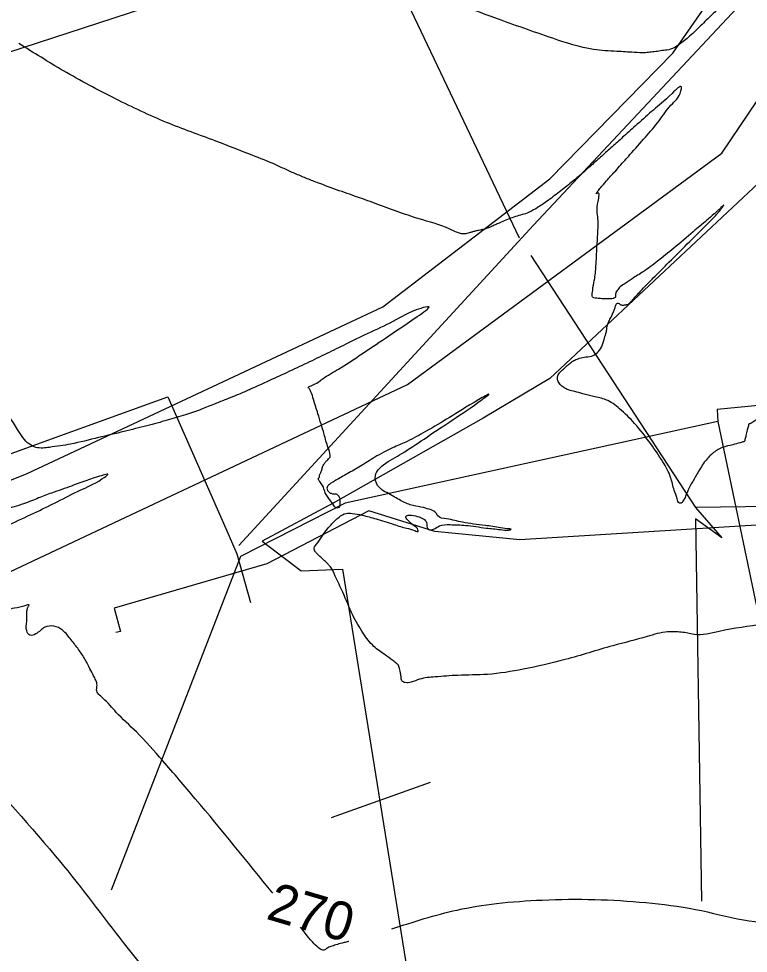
# Model space of a CAD drawing. Extents: x -478464 to -472469, y -1118040 to -1113785.
# Drawn here: x -475618 to -475541.9, y -1115586.5 to -1115489 of the extents above; entities that cross this region are included whole.
import ezdxf

# ---------------------------------------------------------------- set-up
doc = ezdxf.new("R2010")
doc.units = 0
for name, color, linetype in [('el vedeni_NN', 7, 'Continuous'), ('meliorace', 7, 'Continuous'), ('ObPÚ', 7, 'Continuous'), ('plyn_ntl', 7, 'Continuous'), ('plyn_stl', 7, 'Continuous'), ('silnice', 7, 'Continuous'), ('telekomunikační kabel_O2', 7, 'Continuous'), ('VAK_vodovod_přípojky', 7, 'Continuous'), ('Vrstevnice_hlavni', 7, 'Continuous'), ('Vrstevnice_popis', 7, 'Continuous'), ('Vrstevnice_vedlejsi', 7, 'Continuous')]:
    doc.layers.add(name, color=color, linetype=linetype)

msp = doc.modelspace()

# ---------------------------------------------------------------- linework, layer by layer
at = {"layer": 'el vedeni_NN'}
for points in [[(-475377.782, -1115185.638), (-475361.891, -1115178.13), (-475377.677, -1115209.214), (-475398.727, -1115246.374), (-475420.31, -1115282.665), (-475460.363, -1115351.777), (-475479.026, -1115383.225), (-475499.115, -1115417.348), (-475520.351, -1115454.7), (-475542.566, -1115487.377), (-475564.331, -1115510.556), (-475595.07, -1115543.98)], [(-475592.1, -1115463.897), (-475577.122, -1115488.137), (-475565.808, -1115511.875)], [(-475564.609, -1115513.741), (-475547.415, -1115540.02), (-475544.656, -1115543.188), (-475547.4, -1115541.22), (-475546.96, -1115569.997), (-475546.789, -1115581.094)], [(-475483.347, -1115539.435), (-475513.399, -1115539.58), (-475547.415, -1115540.02)]]:
    msp.add_lwpolyline(points, dxfattribs=at)
at = {"layer": 'meliorace'}
msp.add_lwpolyline([(-475519.056, -1115308.142), (-475545.726, -1115356.957), (-475549.536, -1115401.01), (-475559.95, -1115433.157), (-475565.538, -1115475.067), (-475653.93, -1115503.88), (-475665.614, -1115491.736), (-475684.918, -1115489.117), (-475721.748, -1115507.929), (-475797.44, -1115540.314), (-475827.158, -1115551.982), (-475834.778, -1115588.653), (-475852.304, -1115592.225), (-475851.034, -1115628.896), (-475881.514, -1115644.612), (-475900.056, -1115592.463), (-475924.694, -1115605.798), (-475930.282, -1115570.794), (-475926.218, -1115555.554), (-475925.202, -1115548.41), (-475930.536, -1115473.639), (-475966.096, -1115498.642)], dxfattribs=at)
at = {"layer": 'ObPÚ'}
for points in [[(-475728.43, -1115519.24), (-475712.42, -1115512.73), (-475696.58, -1115506.62), (-475678.04, -1115499.14), (-475661.39, -1115542.5), (-475657.48, -1115552.74), (-475617.15, -1115536.48), (-475580.03, -1115519.1), (-475562.62, -1115505.75), (-475549.77, -1115492.64), (-475525.8, -1115458.18)], [(-475534.81, -1115500.57), (-475562.61, -1115526.56), (-475569.57, -1115530.71), (-475585.22, -1115539.58), (-475592.62, -1115543.55), (-475588.56, -1115546.64), (-475584.24, -1115546.47), (-475575.51, -1115600.67), (-475574.56, -1115606.97), (-475568.59, -1115650.37), (-475601.06, -1115656.55), (-475624.46, -1115661.25), (-475654.25, -1115666.44), (-475684.32, -1115671.28), (-475687.18, -1115670.63), (-475693.69, -1115674.84), (-475698.97, -1115680.1), (-475705.68, -1115683.92), (-475709.84, -1115683.94), (-475733.4, -1115683.13)]]:
    msp.add_lwpolyline(points, dxfattribs=at)
at = {"layer": 'plyn_ntl'}
msp.add_line((-475585.38, -1115572.37), (-475575.07, -1115568.66), dxfattribs=at)
at = {"layer": 'plyn_stl'}
msp.add_lwpolyline([(-475699.229, -1115569.389), (-475682.71, -1115562.73), (-475680.94, -1115561.92), (-475675.76, -1115558.44), (-475667.15, -1115553.51), (-475655.03, -1115549.33), (-475634.75, -1115540.12), (-475625, -1115536.6), (-475613.74, -1115532.535), (-475602.48, -1115528.47), (-475596.433, -1115542.197), (-475595.26, -1115544.86), (-475593.843, -1115549.92)], dxfattribs=at)
at = {"layer": 'silnice'}
msp.add_lwpolyline([(-476261.922, -1115907.288), (-476203.622, -1115869.922), (-476022.083, -1115758.582), (-475811.314, -1115629.283), (-475771.826, -1115610.299), (-475706.185, -1115581.566), (-475629.775, -1115551.807), (-475577.467, -1115527.178), (-475544.647, -1115503.063), (-475523.184, -1115471.236), (-475482.102, -1115402.498), (-475367.21, -1115204.445), (-475326.334, -1115129.255), (-475275.418, -1115058.05)], dxfattribs=at)
at = {"layer": 'telekomunikační kabel_O2'}
for points in [[(-475539.93, -1115541.78), (-475565.75, -1115543.38), (-475574.63, -1115542.51), (-475581.49, -1115540.36), (-475592.14, -1115545.91), (-475608.07, -1115550.52)], [(-475608.07, -1115550.52), (-475607.42, -1115552.94)], [(-475607.42, -1115552.94), (-475607.9, -1115553.07)]]:
    msp.add_lwpolyline(points, dxfattribs=at)
at = {"layer": 'VAK_vodovod_přípojky'}
for points in [[(-475400.788, -1115513.502), (-475400.524, -1115515.774), (-475545.153, -1115529.786), (-475545.079, -1115531.049), (-475540.879, -1115551.163)], [(-475545.079, -1115531.049), (-475583.983, -1115539.581), (-475594.886, -1115545.125), (-475608.399, -1115579.932)]]:
    msp.add_lwpolyline(points, dxfattribs=at)
at = {"layer": 'Vrstevnice_hlavni'}
for points in [[(-475591.524, -1115580.265), (-475599.609, -1115570.405), (-475603.006, -1115566.438), (-475605.756, -1115563.433), (-475607.86, -1115561.392), (-475609.247, -1115559.923), (-475609.92, -1115559.026), (-475609.876, -1115558.701), (-475609.874, -1115558.427), (-475609.913, -1115558.202), (-475609.993, -1115558.028), (-475610.223, -1115557.577), (-475610.602, -1115556.848), (-475611.13, -1115555.843), (-475611.784, -1115554.838), (-475612.563, -1115553.834), (-475613.468, -1115552.831), (-475614.385, -1115552.392), (-475615.315, -1115552.518), (-475616.257, -1115553.208), (-475616.885, -1115553.334), (-475617.199, -1115552.896), (-475617.199, -1115551.894), (-475617.188, -1115551.171), (-475617.165, -1115550.727), (-475617.132, -1115550.563), (-475617.087, -1115550.424), (-475617.03, -1115550.311), (-475616.962, -1115550.223), (-475617.522, -1115550.307), (-475618.71, -1115550.562), (-475620.526, -1115550.989), (-475621.889, -1115550.589), (-475622.798, -1115549.362), (-475623.254, -1115547.307), (-475623.56, -1115545.905), (-475623.717, -1115545.155), (-475623.725, -1115545.056), (-475623.491, -1115544.778), (-475623.016, -1115544.322), (-475622.3, -1115543.687), (-475621.816, -1115543.259), (-475621.564, -1115543.038), (-475621.544, -1115543.024), (-475620.687, -1115542.614), (-475618.993, -1115541.808), (-475616.462, -1115540.607), (-475614.01, -1115539.413), (-475611.639, -1115538.226), (-475609.348, -1115537.047), (-475608.735, -1115536.58), (-475609.8, -1115536.824), (-475612.543, -1115537.779), (-475614.606, -1115538.515), (-475615.988, -1115539.03), (-475616.689, -1115539.326), (-475617.534, -1115539.633), (-475618.524, -1115539.952), (-475619.658, -1115540.284), (-475621.024, -1115540.684), (-475622.622, -1115541.153), (-475624.451, -1115541.691), (-475625.936, -1115541.98), (-475627.075, -1115542.019), (-475627.87, -1115541.808), (-475628.975, -1115541.71), (-475630.391, -1115541.727), (-475632.117, -1115541.857), (-475633.269, -1115541.944), (-475633.845, -1115541.987), (-475633.846, -1115541.988), (-475633.935, -1115541.311), (-475634.111, -1115539.956), (-475634.376, -1115537.925), (-475634.629, -1115536.449), (-475634.872, -1115535.531), (-475635.105, -1115535.169), (-475636.099, -1115533.281), (-475637.853, -1115529.865), (-475640.368, -1115524.923), (-475642.128, -1115521.35), (-475643.132, -1115519.146), (-475643.38, -1115518.311), (-475643.745, -1115517.543), (-475644.228, -1115516.841), (-475644.827, -1115516.206), (-475645.294, -1115515.535), (-475645.627, -1115514.826), (-475645.827, -1115514.081), (-475646.265, -1115513.152), (-475646.941, -1115512.04), (-475647.855, -1115510.744), (-475648.331, -1115509.199), (-475648.37, -1115507.406), (-475647.972, -1115505.363), (-475647.723, -1115503.798), (-475647.624, -1115502.709)], [(-475579.109, -1115583.986), (-475572.285, -1115582.012), (-475568.185, -1115581.335), (-475563.397, -1115580.969), (-475557.92, -1115580.913), (-475552.593, -1115581.239), (-475547.416, -1115581.947), (-475542.388, -1115583.036), (-475537.622, -1115583.501), (-475533.118, -1115583.341), (-475528.876, -1115582.557), (-475523.989, -1115580.76), (-475518.456, -1115577.95), (-475512.277, -1115574.126), (-475511.964, -1115573.95)], [(-475583.591, -1115585.283), (-475583.637, -1115585.296), (-475583.865, -1115585.358), (-475584.299, -1115585.475), (-475584.938, -1115585.646), (-475585.465, -1115585.826), (-475585.881, -1115586.013), (-475586.186, -1115586.209), (-475586.627, -1115586.048), (-475587.204, -1115585.533), (-475588.634, -1115583.79)]]:
    msp.add_spline(points, degree=3, dxfattribs=at)
at = {"layer": 'Vrstevnice_vedlejsi'}
for points in [[(-475534.31, -1115479.622), (-475534.205, -1115479.458), (-475534.115, -1115479.315), (-475534.039, -1115479.195), (-475533.977, -1115479.098), (-475533.581, -1115478.429), (-475532.85, -1115477.189), (-475531.786, -1115475.378), (-475530.838, -1115473.747), (-475530.007, -1115472.296), (-475529.292, -1115471.025), (-475528.094, -1115468.828), (-475526.411, -1115465.706), (-475524.244, -1115461.658), (-475523.771, -1115460.37), (-475524.992, -1115461.841), (-475527.906, -1115466.073), (-475530.332, -1115469.593), (-475532.269, -1115472.402), (-475533.717, -1115474.5), (-475534.831, -1115476.125), (-475535.61, -1115477.276), (-475536.055, -1115477.955), (-475536.59, -1115478.738), (-475537.214, -1115479.626), (-475537.927, -1115480.619), (-475538.842, -1115481.699), (-475539.957, -1115482.868), (-475541.273, -1115484.126), (-475542.465, -1115485.298), (-475543.534, -1115486.384), (-475544.478, -1115487.385), (-475545.541, -1115488.465), (-475546.724, -1115489.626), (-475548.026, -1115490.867), (-475549.129, -1115491.733), (-475550.035, -1115492.224), (-475550.742, -1115492.34), (-475551.408, -1115492.437), (-475552.033, -1115492.516), (-475552.616, -1115492.577), (-475553.813, -1115492.551), (-475555.625, -1115492.438), (-475558.052, -1115492.239), (-475562.296, -1115491.075), (-475568.357, -1115488.947), (-475576.235, -1115485.855), (-475583.123, -1115482.7), (-475589.02, -1115479.485), (-475593.926, -1115476.207), (-475598.667, -1115473.276), (-475601.18, -1115471.837)], [(-475587.754, -1115527.573), (-475587.805, -1115527.556), (-475587.308, -1115527.218), (-475586.26, -1115526.559), (-475584.664, -1115525.578), (-475582.499, -1115524.177), (-475579.767, -1115522.355), (-475576.467, -1115520.112), (-475575.24, -1115519.076), (-475576.086, -1115519.248), (-475579.006, -1115520.626), (-475581.614, -1115521.871), (-475583.91, -1115522.984), (-475585.893, -1115523.964), (-475587.936, -1115524.948), (-475590.038, -1115525.937), (-475592.198, -1115526.931), (-475593.833, -1115527.671), (-475594.942, -1115528.158), (-475595.526, -1115528.392), (-475596.393, -1115528.74), (-475597.544, -1115529.202), (-475598.978, -1115529.777), (-475600.642, -1115530.35), (-475602.535, -1115530.92), (-475604.657, -1115531.486), (-475607.048, -1115532.09), (-475609.707, -1115532.73), (-475612.634, -1115533.406), (-475614.811, -1115533.747), (-475616.238, -1115533.753), (-475616.915, -1115533.424), (-475618.153, -1115531.882), (-475619.952, -1115529.128), (-475622.313, -1115525.162), (-475624.203, -1115521.896), (-475625.623, -1115519.329), (-475626.573, -1115517.462), (-475627.223, -1115516.164), (-475627.571, -1115515.436), (-475627.619, -1115515.276), (-475627.688, -1115515.129), (-475627.781, -1115514.995), (-475627.895, -1115514.873), (-475627.985, -1115514.745), (-475628.048, -1115514.609), (-475628.087, -1115514.467), (-475628.17, -1115514.289), (-475628.3, -1115514.076), (-475628.474, -1115513.828), (-475628.566, -1115513.533), (-475628.573, -1115513.19), (-475628.497, -1115512.799), (-475628.449, -1115512.5), (-475628.43, -1115512.292), (-475628.44, -1115512.175), (-475628.549, -1115511.868), (-475628.759, -1115511.372), (-475629.068, -1115510.687), (-475630.244, -1115508.031), (-475632.289, -1115503.403), (-475635.2, -1115496.804), (-475637.318, -1115492.11), (-475638.486, -1115489.639)], [(-475558.11, -1115517.06), (-475557.932, -1115516.133), (-475557.787, -1115514.622), (-475557.674, -1115512.527), (-475557.594, -1115509.849), (-475557.583, -1115508.082), (-475557.642, -1115507.228), (-475557.772, -1115507.286), (-475557.659, -1115507.093), (-475557.304, -1115506.649), (-475556.707, -1115505.954), (-475556.29, -1115505.472), (-475556.053, -1115505.205), (-475555.996, -1115505.151), (-475555.949, -1115505.107), (-475555.912, -1115505.072), (-475555.885, -1115505.046), (-475555.33, -1115504.422), (-475554.247, -1115503.201), (-475552.636, -1115501.382), (-475551.213, -1115499.67), (-475549.977, -1115498.066), (-475548.93, -1115496.57), (-475548.886, -1115496.153), (-475549.846, -1115496.815), (-475551.81, -1115498.555), (-475553.486, -1115500.044), (-475554.874, -1115501.282), (-475555.974, -1115502.268), (-475557.062, -1115503.241), (-475558.141, -1115504.199), (-475559.209, -1115505.143), (-475560.369, -1115506.11), (-475561.62, -1115507.099), (-475562.963, -1115508.111), (-475564.087, -1115508.85), (-475564.994, -1115509.316), (-475565.682, -1115509.509), (-475566.362, -1115509.731), (-475567.034, -1115509.982), (-475567.698, -1115510.262), (-475568.229, -1115510.491), (-475568.627, -1115510.669), (-475568.892, -1115510.797), (-475569.232, -1115510.916), (-475569.646, -1115511.028), (-475570.135, -1115511.133), (-475570.485, -1115511.213), (-475570.697, -1115511.269), (-475570.77, -1115511.3), (-475570.911, -1115511.342), (-475571.119, -1115511.394), (-475571.395, -1115511.457), (-475573.107, -1115510.961), (-475576.256, -1115509.908), (-475580.843, -1115508.297), (-475584.291, -1115507.072), (-475586.602, -1115506.234), (-475587.775, -1115505.781), (-475588.931, -1115505.305), (-475590.072, -1115504.804), (-475591.195, -1115504.279), (-475593.662, -1115503.278), (-475597.47, -1115501.8), (-475602.621, -1115499.845), (-475607.922, -1115497.397), (-475613.372, -1115494.456), (-475618.033, -1115491.609)], [(-475546.513, -1115535.309), (-475547.266, -1115536.546), (-475547.849, -1115537.569), (-475548.26, -1115538.376), (-475548.501, -1115538.969), (-475548.719, -1115539.366), (-475548.915, -1115539.566), (-475549.088, -1115539.57), (-475549.327, -1115539.123), (-475549.632, -1115538.226), (-475550.002, -1115536.878), (-475550.814, -1115535.267), (-475552.068, -1115533.392), (-475553.764, -1115531.254), (-475555.329, -1115529.716), (-475556.765, -1115528.778), (-475558.07, -1115528.441), (-475559.153, -1115528.157), (-475560.014, -1115527.926), (-475560.653, -1115527.748), (-475561.161, -1115527.498), (-475561.538, -1115527.177), (-475561.785, -1115526.785), (-475561.809, -1115526.387), (-475561.61, -1115525.984), (-475561.189, -1115525.576), (-475560.801, -1115525.224), (-475560.446, -1115524.931), (-475560.123, -1115524.694), (-475559.652, -1115524.499), (-475559.033, -1115524.344), (-475558.264, -1115524.231), (-475557.662, -1115523.886), (-475557.226, -1115523.31), (-475556.955, -1115522.504), (-475556.77, -1115521.885), (-475556.669, -1115521.455), (-475556.654, -1115521.213), (-475556.563, -1115520.897), (-475556.398, -1115520.505), (-475556.158, -1115520.039), (-475555.967, -1115519.62), (-475555.825, -1115519.246), (-475555.732, -1115518.92), (-475555.616, -1115518.74), (-475555.477, -1115518.708), (-475555.314, -1115518.823), (-475555.147, -1115518.891), (-475554.977, -1115518.912), (-475554.802, -1115518.886), (-475554.66, -1115518.864), (-475554.549, -1115518.847), (-475554.471, -1115518.833), (-475554.356, -1115518.754), (-475554.203, -1115518.611), (-475554.013, -1115518.402), (-475553.726, -1115518.089), (-475553.343, -1115517.672), (-475552.863, -1115517.151), (-475551.811, -1115516.075), (-475550.186, -1115514.443), (-475547.988, -1115512.256), (-475546.434, -1115510.705), (-475545.525, -1115509.788), (-475545.259, -1115509.506), (-475545.003, -1115509.213), (-475544.757, -1115508.909), (-475544.52, -1115508.595), (-475544.462, -1115508.482), (-475544.581, -1115508.57), (-475544.879, -1115508.86), (-475545.127, -1115509.095), (-475545.323, -1115509.276), (-475545.469, -1115509.402), (-475546.241, -1115510.061), (-475547.641, -1115511.252), (-475549.668, -1115512.974), (-475551.409, -1115514.366), (-475552.865, -1115515.426), (-475554.035, -1115516.154), (-475554.868, -1115516.712), (-475555.365, -1115517.1), (-475555.524, -1115517.318), (-475555.637, -1115517.471), (-475555.703, -1115517.561), (-475555.723, -1115517.587), (-475555.739, -1115517.681), (-475555.752, -1115517.842), (-475555.761, -1115518.07), (-475556.005, -1115518.213), (-475556.482, -1115518.268), (-475557.194, -1115518.238), (-475557.711, -1115518.193), (-475558.033, -1115518.133), (-475558.16, -1115518.06), (-475558.186, -1115517.702), (-475558.11, -1115517.06)], [(-475528, -1115522.718), (-475528.218, -1115522.855), (-475533.174, -1115525.967), (-475536.873, -1115528.287), (-475539.317, -1115529.813), (-475540.505, -1115530.545), (-475541.317, -1115531.036), (-475541.751, -1115531.286), (-475541.809, -1115531.294), (-475541.893, -1115531.503), (-475542.004, -1115531.912), (-475542.143, -1115532.523), (-475542.247, -1115532.934), (-475542.318, -1115533.146), (-475542.355, -1115533.159), (-475542.754, -1115533.267), (-475543.515, -1115533.471), (-475544.637, -1115533.772), (-475545.636, -1115534.384), (-475546.513, -1115535.309)], [(-475569.376, -1115541.9), (-475571.74, -1115541.553), (-475573.384, -1115541.215), (-475574.306, -1115540.885), (-475574.508, -1115540.562), (-475575.005, -1115540.279), (-475575.796, -1115540.034), (-475576.882, -1115539.827), (-475578.041, -1115539.373), (-475579.274, -1115538.669), (-475580.58, -1115537.718), (-475580.81, -1115536.684), (-475579.965, -1115535.57), (-475578.044, -1115534.374), (-475575.741, -1115532.876), (-475573.057, -1115531.077), (-475569.992, -1115528.977), (-475568.976, -1115528.205), (-475570.01, -1115528.761), (-475573.093, -1115530.645), (-475575.587, -1115532.098), (-475577.493, -1115533.12), (-475578.809, -1115533.711), (-475579.94, -1115534.265), (-475580.885, -1115534.781), (-475581.644, -1115535.26), (-475582.375, -1115535.706), (-475583.075, -1115536.12), (-475583.746, -1115536.502), (-475584.366, -1115536.857), (-475584.935, -1115537.187), (-475585.453, -1115537.49), (-475585.769, -1115537.765), (-475585.885, -1115538.013), (-475585.799, -1115538.233), (-475585.681, -1115538.399), (-475585.533, -1115538.51), (-475585.353, -1115538.566), (-475585.198, -1115538.596), (-475585.069, -1115538.601), (-475584.966, -1115538.581), (-475584.85, -1115538.631), (-475584.723, -1115538.749), (-475584.584, -1115538.937), (-475584.521, -1115539.209), (-475584.536, -1115539.565), (-475584.628, -1115540.004), (-475584.835, -1115540.089), (-475585.156, -1115539.82), (-475585.592, -1115539.196), (-475585.885, -1115538.778), (-475586.035, -1115538.565), (-475586.042, -1115538.559), (-475586.049, -1115538.539), (-475586.056, -1115538.505), (-475586.064, -1115538.458), (-475586.095, -1115538.349), (-475586.151, -1115538.18), (-475586.23, -1115537.951), (-475586.335, -1115537.728), (-475586.464, -1115537.512), (-475586.618, -1115537.301), (-475586.721, -1115537.154), (-475586.775, -1115537.071), (-475586.779, -1115537.052), (-475586.767, -1115537.018), (-475586.737, -1115536.97), (-475586.691, -1115536.908), (-475586.663, -1115536.849), (-475586.654, -1115536.791), (-475586.664, -1115536.735), (-475586.644, -1115536.646), (-475586.594, -1115536.523), (-475586.514, -1115536.366), (-475586.442, -1115536.189), (-475586.38, -1115535.992), (-475586.326, -1115535.775), (-475586.21, -1115535.544), (-475586.031, -1115535.299), (-475585.789, -1115535.04), (-475585.626, -1115534.862), (-475585.541, -1115534.765), (-475585.535, -1115534.748), (-475585.529, -1115534.735), (-475585.525, -1115534.723), (-475585.522, -1115534.715), (-475585.522, -1115534.684), (-475585.524, -1115534.632), (-475585.528, -1115534.557), (-475585.745, -1115533.801), (-475586.174, -1115532.362), (-475586.816, -1115530.242), (-475587.27, -1115528.769), (-475587.539, -1115527.944), (-475587.62, -1115527.766), (-475587.692, -1115527.643), (-475587.754, -1115527.573)], [(-475517.828, -1115550.496), (-475520.343, -1115549.824), (-475523.811, -1115549.108), (-475525.873, -1115548.952), (-475526.527, -1115549.357), (-475529.155, -1115550.032), (-475533.756, -1115550.978), (-475540.329, -1115552.193), (-475544.932, -1115552.956), (-475547.563, -1115553.265), (-475548.222, -1115553.122), (-475548.901, -1115553.03), (-475549.6, -1115552.987), (-475550.319, -1115552.994), (-475552.462, -1115553.481), (-475556.029, -1115554.446), (-475561.022, -1115555.89), (-475565.385, -1115556.886), (-475569.118, -1115557.432), (-475572.222, -1115557.53), (-475574.585, -1115557.697), (-475576.205, -1115557.934), (-475577.084, -1115558.241), (-475577.699, -1115558.294), (-475578.049, -1115558.095), (-475578.134, -1115557.644), (-475578.21, -1115557.261), (-475578.276, -1115556.949), (-475578.332, -1115556.706), (-475578.399, -1115556.52), (-475578.478, -1115556.391), (-475578.568, -1115556.319), (-475579.012, -1115555.983), (-475579.812, -1115555.383), (-475580.966, -1115554.517), (-475582.085, -1115553.143), (-475583.17, -1115551.258), (-475584.22, -1115548.865), (-475585.001, -1115547.179), (-475585.513, -1115546.202), (-475585.758, -1115545.932), (-475586.036, -1115545.652), (-475586.348, -1115545.361), (-475586.694, -1115545.06), (-475586.954, -1115544.797), (-475587.129, -1115544.571), (-475587.218, -1115544.383), (-475586.968, -1115543.863), (-475586.378, -1115543.01), (-475585.448, -1115541.825), (-475584.614, -1115541.034), (-475583.877, -1115540.637), (-475583.236, -1115540.633), (-475582.192, -1115540.822), (-475580.747, -1115541.205), (-475578.899, -1115541.781), (-475577.553, -1115542.19), (-475576.708, -1115542.434), (-475576.364, -1115542.511), (-475576.372, -1115542.352), (-475576.731, -1115541.958), (-475577.442, -1115541.327), (-475577.627, -1115540.948), (-475577.285, -1115540.821), (-475576.417, -1115540.945), (-475575.814, -1115541.202), (-475575.478, -1115541.591), (-475575.407, -1115542.113), (-475575.16, -1115542.347), (-475574.738, -1115542.292), (-475574.14, -1115541.947), (-475573.027, -1115541.811), (-475571.398, -1115541.882), (-475569.254, -1115542.16), (-475567.762, -1115542.329), (-475566.921, -1115542.387), (-475566.731, -1115542.336), (-475566.657, -1115542.297), (-475566.698, -1115542.271), (-475566.855, -1115542.258), (-475567.747, -1115542.135), (-475569.376, -1115541.9)], [(-475644.775, -1115561.525), (-475644.553, -1115561.716), (-475644.419, -1115561.902), (-475644.372, -1115562.084), (-475644.413, -1115562.261), (-475644.488, -1115562.402), (-475644.597, -1115562.509), (-475644.741, -1115562.58), (-475644.643, -1115562.97), (-475644.303, -1115563.677), (-475643.722, -1115564.701), (-475643.33, -1115565.387), (-475643.125, -1115565.735), (-475643.108, -1115565.744), (-475643.062, -1115565.734), (-475642.987, -1115565.704), (-475642.884, -1115565.655), (-475641.418, -1115564.977), (-475638.589, -1115563.669), (-475634.397, -1115561.731), (-475631.683, -1115560.443), (-475630.448, -1115559.803), (-475630.69, -1115559.813), (-475630.89, -1115559.744), (-475631.046, -1115559.596), (-475631.16, -1115559.37), (-475631.274, -1115559.148), (-475631.391, -1115558.93), (-475631.51, -1115558.715), (-475631.587, -1115558.507), (-475631.624, -1115558.305), (-475631.62, -1115558.109), (-475631.557, -1115557.94), (-475631.434, -1115557.799), (-475631.252, -1115557.684), (-475630.269, -1115557.367), (-475628.485, -1115556.848), (-475625.901, -1115556.127), (-475624.539, -1115555.867), (-475624.397, -1115556.068), (-475625.476, -1115556.729), (-475626.393, -1115557.382), (-475627.149, -1115558.024), (-475627.742, -1115558.658), (-475628.066, -1115559.149), (-475628.122, -1115559.498), (-475627.91, -1115559.704), (-475623.276, -1115565.32), (-475614.22, -1115576.346), (-475600.742, -1115592.782), (-475591.753, -1115603.737), (-475587.254, -1115609.211), (-475587.245, -1115609.205), (-475587.232, -1115609.199), (-475587.215, -1115609.194), (-475587.195, -1115609.188), (-475587.13, -1115609.17), (-475587.02, -1115609.138), (-475586.864, -1115609.093), (-475583.35, -1115609.028), (-475576.475, -1115608.944), (-475566.24, -1115608.839), (-475556.285, -1115609.448), (-475546.609, -1115610.771), (-475537.213, -1115612.807), (-475530.312, -1115614.046), (-475528.152, -1115614.336)], [(-475811.843, -1115589.098), (-475806.668, -1115588.433), (-475802.959, -1115587.87), (-475800.717, -1115587.407), (-475799.941, -1115587.045), (-475798.521, -1115586.629), (-475796.458, -1115586.16), (-475793.75, -1115585.638), (-475790.96, -1115585.804), (-475788.087, -1115586.66), (-475785.131, -1115588.204), (-475782.737, -1115589.574), (-475780.904, -1115590.769), (-475779.633, -1115591.79), (-475777.973, -1115592.489), (-475775.924, -1115592.864), (-475773.485, -1115592.916), (-475767.267, -1115594.67), (-475757.27, -1115598.125), (-475743.493, -1115603.281), (-475733.601, -1115607.294), (-475727.593, -1115610.164), (-475725.471, -1115611.89), (-475723.13, -1115612.984), (-475720.569, -1115613.444), (-475717.788, -1115613.272), (-475715.213, -1115613.282), (-475712.844, -1115613.475), (-475710.68, -1115613.85), (-475709.072, -1115614.206), (-475708.019, -1115614.545), (-475707.523, -1115614.865), (-475706.707, -1115615.319), (-475705.572, -1115615.908), (-475704.116, -1115616.63), (-475698.148, -1115618.585), (-475687.667, -1115621.772), (-475672.674, -1115626.19), (-475662.363, -1115629.476), (-475656.736, -1115631.63), (-475655.792, -1115632.652), (-475654.354, -1115633.953), (-475652.421, -1115635.534), (-475649.994, -1115637.394), (-475648.293, -1115638.659), (-475647.317, -1115639.328), (-475647.067, -1115639.402), (-475646.579, -1115639.624), (-475645.853, -1115639.994), (-475644.888, -1115640.511), (-475643.837, -1115641.049), (-475642.7, -1115641.606), (-475641.477, -1115642.184), (-475640.547, -1115642.576), (-475639.911, -1115642.782), (-475639.569, -1115642.802), (-475638.286, -1115643.971), (-475636.063, -1115646.289), (-475632.9, -1115649.755), (-475630.403, -1115652.368), (-475628.572, -1115654.126), (-475627.408, -1115655.03), (-475626.263, -1115655.851), (-475625.136, -1115656.588), (-475624.027, -1115657.241), (-475623.122, -1115657.91), (-475622.421, -1115658.597), (-475621.923, -1115659.301), (-475621.576, -1115659.828), (-475621.379, -1115660.18), (-475621.333, -1115660.356), (-475621.215, -1115660.503), (-475621.024, -1115660.621), (-475620.761, -1115660.71), (-475620.54, -1115660.782), (-475620.362, -1115660.836), (-475620.225, -1115660.873), (-475619.903, -1115660.963), (-475619.394, -1115661.104), (-475618.699, -1115661.296), (-475618.02, -1115661.581), (-475617.356, -1115661.956), (-475616.706, -1115662.423), (-475616.078, -1115662.701), (-475615.47, -1115662.79), (-475614.884, -1115662.691), (-475614.427, -1115662.633), (-475614.101, -1115662.615), (-475613.905, -1115662.638), (-475613.615, -1115662.702), (-475613.229, -1115662.808), (-475612.749, -1115662.956), (-475611.641, -1115663.191), (-475609.905, -1115663.514), (-475607.54, -1115663.924), (-475605.647, -1115664.255), (-475604.226, -1115664.508)]]:
    msp.add_spline(points, degree=3, dxfattribs=at)

# ---------------------------------------------------------------- texts
at = {"layer": 'Vrstevnice_popis'}
msp.add_text(' 270 ', height=4, rotation=343.50155, dxfattribs=at).set_placement((-475593.767, -1115582.478))

doc.saveas('drawing.dxf')
